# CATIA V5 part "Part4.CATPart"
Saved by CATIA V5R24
Part number: Link3-2
Bounding box of the stored display mesh (mm): x -20 to 0, y -23.098 to 5.02, z -29.98 to 22.498
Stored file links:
  G:\_CAD수업\DMU_paradoxes\2\Part4.CATPart
  G:\_CAD수업\DMU_paradoxes\2\Part3.CATPart
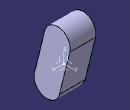
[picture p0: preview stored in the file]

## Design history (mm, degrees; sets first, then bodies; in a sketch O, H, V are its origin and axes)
AxisSystem1: origin (0, 0, 0), X (1, 0, 0), Y (0, 1, 0), Z (0, 0, 1)
Body1 (main body)
  Sketch1 on YZ plane of AxisSystem1, origin (0, 0, 0), H (0, 1, 0), V (0, 0, 1)
    line L1 (-25.2258, -27.2573) -> (-5.8229, -32.108)
    line L2 (-5.8229, -32.108) -> (7.148, 19.7755)
    line L3 (7.148, 19.7755) -> (-12.2549, 24.6262)
    line L4 (-12.2549, 24.6262) -> (-25.2258, -27.2573)
    length L1 = 20
    parallelism: L4 L2, L1 L3
    perpendicularity: L1 L2
  Pad1: profile Sketch1, direction (-1, 0, 0), length 20
  TritangentFillet1: Face1 face of Pad1 from Sketch1.L4, Face2 face of Pad1 from Sketch1.L2, RemoveFace face of Pad1 from Sketch1.L1
  TritangentFillet2: Face1 face of Pad1 from Sketch1.L4, Face2 face of Pad1 from Sketch1.L2, RemoveFace face of Pad1 from Sketch1.L3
